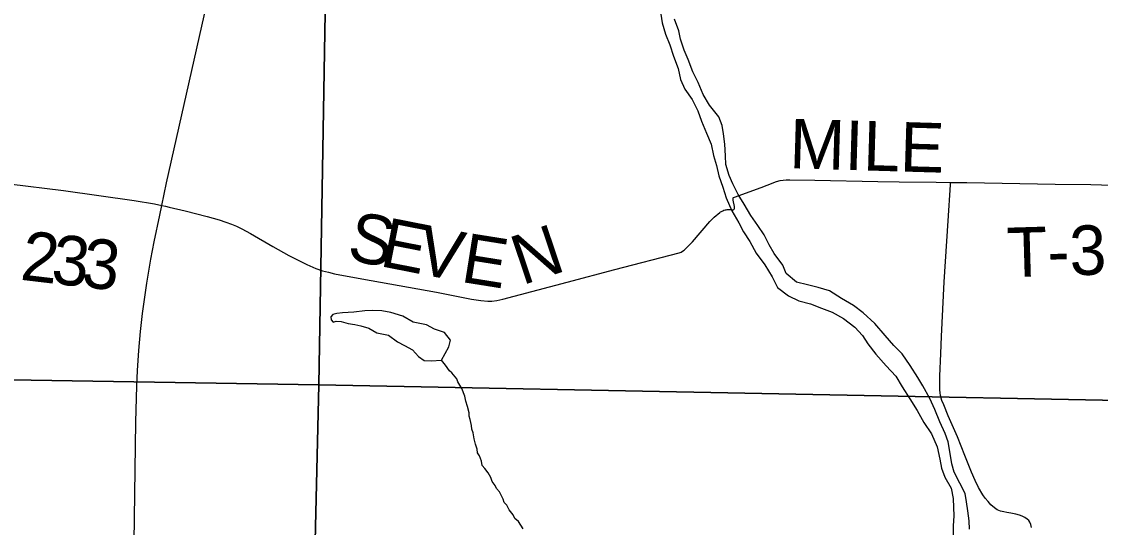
# Model space of a CAD drawing. Extents: x -8.8 to 41.4, y 0 to 34.6.
# Drawn here: x -7.751 to -6.515, y 19.52 to 20.1 of the extents above; entities that cross this region are included whole.
import ezdxf

# ---------------------------------------------------------------- set-up
doc = ezdxf.new("R2010")
doc.units = 0
for name, color, linetype in [('GM_X_Corporation', 7, 'Continuous'), ('GM_X_Major_Lake', 7, 'Continuous'), ('GM_X_Minor_River', 7, 'Continuous'), ('GM_X_Section_Text', 7, 'Continuous'), ('GM_X_Township_Road', 7, 'Continuous'), ('GM_X_US_Route', 7, 'Continuous')]:
    doc.layers.add(name, color=color, linetype=linetype)

msp = doc.modelspace()

# ---------------------------------------------------------------- linework, layer by layer
at = {"layer": 'GM_X_Corporation'}
for points in [[(-8.3959, 20.6927), (-7.3933, 20.6722), (-7.4104, 19.6835), (-8.4231, 19.7001)], [(-7.3933, 20.6722), (-6.3797, 20.6503), (-6.3951, 19.6638), (-7.4104, 19.6835)], [(-7.4104, 19.6835), (-7.4338, 18.6729), (-8.4109, 18.686), (-8.4457, 18.6861), (-8.4231, 19.7001)], [(-7.4104, 19.6835), (-6.3951, 19.6638), (-6.415, 18.6581), (-7.4209, 18.6726), (-7.4338, 18.6729)]]:
    msp.add_lwpolyline(points, close=True, dxfattribs=at)
at = {"layer": 'GM_X_Major_Lake'}
for points in [[(-7.0185, 20.1087), (-7.0169, 20.0988), (-7.013, 20.0858), (-7.008, 20.0735), (-7.0038, 20.0605), (-6.9984, 20.0463), (-6.9957, 20.0337), (-6.9907, 20.0229), (-6.9826, 20.011), (-6.9758, 19.9979), (-6.9719, 19.986), (-6.9662, 19.9722), (-6.9608, 19.9596), (-6.9581, 19.9466), (-6.9546, 19.9351), (-6.9518, 19.9233), (-6.9472, 19.9103), (-6.9434, 19.898), (-6.9369, 19.8831), (-6.9289, 19.8696), (-6.9235, 19.8592), (-6.9165, 19.848), (-6.9093, 19.8346), (-6.899, 19.8214), (-6.8906, 19.8075), (-6.8848, 19.7953), (-6.8722, 19.7855), (-6.8602, 19.7798), (-6.847, 19.7765), (-6.8342, 19.7716), (-6.8222, 19.7668), (-6.8091, 19.7596), (-6.7961, 19.7498), (-6.7872, 19.7401), (-6.781, 19.7305), (-6.7718, 19.7189), (-6.76, 19.7053), (-6.7489, 19.6936), (-6.7417, 19.6813), (-6.7329, 19.6674), (-6.7245, 19.654), (-6.7169, 19.6405), (-6.7081, 19.6274), (-6.7016, 19.6124), (-6.6986, 19.5983), (-6.6969, 19.588), (-6.693, 19.5777), (-6.6858, 19.565), (-6.6834, 19.5532), (-6.6829, 19.5429), (-6.6824, 19.5334), (-6.6834, 19.522), (-6.6833, 19.5107)], [(-6.7101, 19.668), (-6.7181, 19.6823), (-6.7239, 19.6919), (-6.7327, 19.7058), (-6.7418, 19.7193), (-6.7515, 19.7286), (-6.7614, 19.7402), (-6.7732, 19.7538), (-6.7866, 19.7663), (-6.7977, 19.7745), (-6.8112, 19.7828), (-6.825, 19.7915), (-6.8382, 19.7952), (-6.8503, 19.7982), (-6.8627, 19.8012), (-6.8746, 19.8113), (-6.8785, 19.8209), (-6.8884, 19.8341), (-6.8942, 19.8441), (-6.9, 19.8556), (-6.9073, 19.8664), (-6.9154, 19.878), (-6.9227, 19.8907), (-6.9296, 19.9019), (-6.9357, 19.9142), (-6.9401, 19.9238), (-6.9439, 19.9364), (-6.9444, 19.9463), (-6.9452, 19.9596), (-6.9465, 19.9714), (-6.9481, 19.9809), (-6.952, 19.9909), (-6.9627, 20.0044), (-6.97, 20.0167), (-6.9757, 20.0305), (-6.9815, 20.0425), (-6.9872, 20.0566), (-6.9915, 20.0674), (-6.9957, 20.08), (-6.9977, 20.0896), (-7.0027, 20.103)], [(-6.6645, 19.5182), (-6.6651, 19.5277), (-6.6667, 19.5391), (-6.6679, 19.5494), (-6.6696, 19.5589), (-6.6758, 19.5708), (-6.6823, 19.5835), (-6.6847, 19.593), (-6.687, 19.6071), (-6.689, 19.6182), (-6.6925, 19.6277), (-6.6987, 19.6412), (-6.7044, 19.6554), (-6.7101, 19.668)]]:
    msp.add_lwpolyline(points, dxfattribs=at)
at = {"layer": 'GM_X_Minor_River'}
for points in [[(-7.2697, 19.712), (-7.2612, 19.7271), (-7.2603, 19.7316), (-7.2594, 19.735), (-7.2664, 19.7436), (-7.2776, 19.7474), (-7.2869, 19.7526), (-7.302, 19.7553), (-7.314, 19.7622), (-7.3279, 19.7664), (-7.338, 19.7686), (-7.3486, 19.7689), (-7.3574, 19.7684), (-7.3703, 19.7669), (-7.3832, 19.7662), (-7.3897, 19.7656), (-7.3943, 19.7643), (-7.3967, 19.7617), (-7.396, 19.7582), (-7.3938, 19.7555), (-7.3904, 19.7565), (-7.3847, 19.7564), (-7.3768, 19.7538), (-7.3689, 19.7528), (-7.3621, 19.7511), (-7.3531, 19.7486), (-7.3437, 19.7433)], [(-7.3437, 19.7433), (-7.3306, 19.7406), (-7.3202, 19.7331), (-7.312, 19.7287), (-7.303, 19.7238), (-7.296, 19.716), (-7.2897, 19.7116), (-7.2814, 19.711), (-7.2697, 19.712)], [(-7.1762, 19.5185), (-7.1787, 19.5228), (-7.1816, 19.5267), (-7.1857, 19.5302), (-7.1874, 19.5345), (-7.1922, 19.5403), (-7.195, 19.5454), (-7.198, 19.5485), (-7.199, 19.5524), (-7.2032, 19.5609), (-7.2065, 19.5648), (-7.2083, 19.5683), (-7.2116, 19.5726), (-7.2133, 19.5772), (-7.2161, 19.5826), (-7.2201, 19.5877), (-7.2231, 19.5912), (-7.224, 19.5962), (-7.2261, 19.602), (-7.2283, 19.6055), (-7.2289, 19.6097), (-7.2306, 19.6154), (-7.2323, 19.6216), (-7.2335, 19.6284), (-7.2349, 19.6327), (-7.2355, 19.6369), (-7.2368, 19.6438), (-7.2382, 19.6476), (-7.2381, 19.6514), (-7.2401, 19.6587), (-7.2418, 19.6648), (-7.2431, 19.6706), (-7.2466, 19.6795), (-7.2509, 19.6872), (-7.2523, 19.6903), (-7.2577, 19.6973), (-7.2607, 19.6997), (-7.265, 19.7063), (-7.2697, 19.712)]]:
    msp.add_lwpolyline(points, dxfattribs=at)
at = {"layer": 'GM_X_Township_Road'}
for points in [[(-7.5901, 19.8894), (-7.5861, 19.8885), (-7.5817, 19.8875), (-7.5635, 19.883), (-7.5382, 19.8765), (-7.5244, 19.8727), (-7.5168, 19.8703), (-7.5104, 19.8679), (-7.5046, 19.8655), (-7.4985, 19.8625), (-7.4886, 19.8572), (-7.463, 19.8421), (-7.4445, 19.8319), (-7.4239, 19.8215), (-7.4136, 19.8171), (-7.406, 19.8145), (-7.3994, 19.8127), (-7.3922, 19.811), (-7.361, 19.8051), (-7.2754, 19.7898), (-7.2352, 19.7818), (-7.2247, 19.7802), (-7.2167, 19.7795), (-7.2119, 19.7795), (-7.2063, 19.7803), (-7.1995, 19.7818), (-7.1256, 19.8015), (-7.071, 19.816), (-6.9973, 19.8349), (-6.9952, 19.8358), (-6.9934, 19.8368), (-6.9916, 19.8382), (-6.99, 19.8395), (-6.986, 19.8437), (-6.9822, 19.8478), (-6.9623, 19.8708), (-6.9571, 19.8759), (-6.9508, 19.8813), (-6.9498, 19.8821), (-6.9487, 19.8826), (-6.9473, 19.8833), (-6.9461, 19.8838), (-6.9448, 19.8842), (-6.9435, 19.8845), (-6.9422, 19.8847), (-6.9407, 19.8848), (-6.9398, 19.8848), (-6.9386, 19.8847), (-6.9376, 19.8845), (-6.9366, 19.8844), (-6.9356, 19.8844), (-6.9347, 19.8847), (-6.9342, 19.8852), (-6.9339, 19.8859), (-6.9338, 19.8871), (-6.934, 19.8883), (-6.9355, 19.8955), (-6.9356, 19.8965), (-6.9356, 19.8974), (-6.9354, 19.898), (-6.9349, 19.8985), (-6.9338, 19.899), (-6.9034, 19.91), (-6.8966, 19.9128), (-6.8859, 19.9168), (-6.8816, 19.9179), (-6.8781, 19.9184), (-6.8748, 19.9186), (-6.8706, 19.9186), (-6.842, 19.9184), (-6.7695, 19.9169), (-6.7453, 19.9165), (-6.703, 19.9161), (-6.6863, 19.9158), (-6.6676, 19.9158), (-6.5664, 19.9138), (-6.5255, 19.9133), (-6.4884, 19.9124)], [(-7.7651, 19.9141), (-7.7028, 19.9066), (-7.6221, 19.8951), (-7.5987, 19.8913), (-7.5901, 19.8894)], [(-6.5935, 19.5199), (-6.5943, 19.5233), (-6.5953, 19.5259), (-6.5968, 19.528), (-6.5985, 19.5297), (-6.6012, 19.5314), (-6.6042, 19.5329), (-6.6074, 19.5341), (-6.6114, 19.5352), (-6.6172, 19.5363), (-6.6217, 19.5371), (-6.6254, 19.5378), (-6.6292, 19.5388), (-6.633, 19.5404), (-6.6361, 19.5424), (-6.64, 19.5459), (-6.6434, 19.5496), (-6.6468, 19.5537), (-6.6492, 19.5575), (-6.6544, 19.566), (-6.6582, 19.5738), (-6.6623, 19.5833), (-6.6699, 19.6024), (-6.6784, 19.6241), (-6.6889, 19.6481), (-6.6942, 19.6606), (-6.6962, 19.6657), (-6.6977, 19.6714), (-6.6984, 19.6745), (-6.6987, 19.678), (-6.6987, 19.681), (-6.6986, 19.6937), (-6.6974, 19.7194), (-6.6966, 19.7391), (-6.6938, 19.8016), (-6.6889, 19.8718), (-6.6864, 19.9132), (-6.6863, 19.9158)]]:
    msp.add_lwpolyline(points, dxfattribs=at)
at = {"layer": 'GM_X_US_Route'}
msp.add_lwpolyline([(-7.6348, 18.6761), (-7.6327, 18.7742), (-7.6312, 18.8767), (-7.6298, 18.9798), (-7.6265, 19.1979), (-7.6242, 19.3538), (-7.6219, 19.5036), (-7.6199, 19.6409), (-7.6188, 19.6825), (-7.618, 19.6999), (-7.6165, 19.7229), (-7.6146, 19.7446), (-7.6122, 19.7656), (-7.6098, 19.7841), (-7.6074, 19.8001), (-7.6028, 19.8277), (-7.5989, 19.8478), (-7.5925, 19.8782), (-7.5901, 19.8894), (-7.5847, 19.9152), (-7.5241, 20.1851)], dxfattribs=at)

# ---------------------------------------------------------------- texts
at = {"layer": 'GM_X_Section_Text'}
for s, height, rotation, p in [('MILE', 0.05682, 358.3152, (-6.8715, 19.9321)), ('S', 0.0568, 348.8541, (-7.3795, 19.8275)), ('E', 0.0568, 348.8514, (-7.3419, 19.8201)), ('T-331', 0.05682, 1.6848, (-6.621, 19.807)), ('2', 0.0568, 353.2538, (-7.7535, 19.8043)), ('3', 0.0568, 353.5236, (-7.7184, 19.8002)), ('V', 0.0568, 348.8577, (-7.3002, 19.8119)), ('E', 0.0568, 350.9432, (-7.2489, 19.8019)), ('N', 0.0568, 18.574, (-7.1774, 19.7976)), ('3', 0.0568, 353.5751, (-7.6836, 19.7962))]:
    msp.add_text(s, height=height, rotation=rotation, dxfattribs=at).set_placement(p)

doc.saveas('drawing.dxf')
